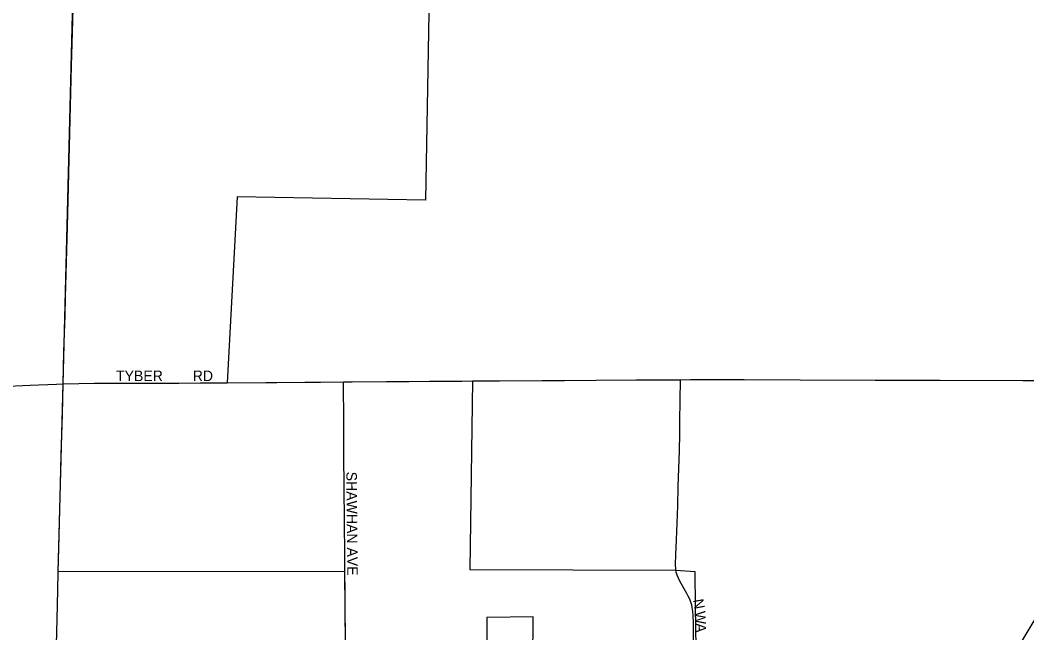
# Model space of a CAD drawing. Extents: x 1772825 to 1773716, y 1138558 to 1139032.
# Drawn here: x 1773338.15 to 1773356.3, y 1138902.61 to 1138913.65 of the extents above; entities that cross this region are included whole.
import ezdxf

# ---------------------------------------------------------------- set-up
doc = ezdxf.new("R2010")
doc.units = 0
for name, color, linetype in [('GM_X_City_Street', 7, 'Continuous'), ('GM_X_City_Street_Text', 7, 'Continuous'), ('GM_X_Corporation', 7, 'Continuous'), ('GM_X_County_Road', 7, 'Continuous'), ('GM_X_Township_Road', 7, 'Continuous')]:
    doc.layers.add(name, color=color, linetype=linetype)

msp = doc.modelspace()

# ---------------------------------------------------------------- linework, layer by layer
at = {"layer": 'GM_X_City_Street'}
for points in [[(1773338.923, 1138907.099), (1773339.493, 1138907.113), (1773340.34, 1138907.113), (1773341.011, 1138907.115), (1773341.396, 1138907.117), (1773341.884, 1138907.12)], [(1773344.007, 1138903.718), (1773344.003, 1138903.998), (1773343.998, 1138904.633), (1773343.987, 1138905.822), (1773343.984, 1138906.512), (1773343.979, 1138907.028), (1773343.978, 1138907.136)], [(1773344.019, 1138902.031), (1773344.018, 1138902.406), (1773344.016, 1138902.7), (1773344.013, 1138902.883), (1773344.01, 1138903.107), (1773344.009, 1138903.327), (1773344.007, 1138903.718)], [(1773350.292, 1138901.88), (1773350.293, 1138902.175), (1773350.293, 1138902.608), (1773350.289, 1138902.814), (1773350.286, 1138902.913), (1773350.285, 1138902.946), (1773350.282, 1138902.981), (1773350.28, 1138903.006), (1773350.275, 1138903.035), (1773350.269, 1138903.07), (1773350.259, 1138903.112), (1773350.238, 1138903.185), (1773350.224, 1138903.223), (1773350.198, 1138903.273), (1773350.17, 1138903.325), (1773350.047, 1138903.542), (1773349.996, 1138903.653), (1773349.984, 1138903.686), (1773349.979, 1138903.708), (1773349.975, 1138903.741)]]:
    msp.add_lwpolyline(points, dxfattribs=at)
at = {"layer": 'GM_X_Corporation'}
for points in [[(1773334.227, 1138900.103), (1773338.755, 1138900.152), (1773338.788, 1138900.602), (1773342.273, 1138900.611), (1773342.286, 1138900.627), (1773342.309, 1138900.637), (1773342.368, 1138900.64), (1773342.556, 1138900.646), (1773344.037, 1138900.647), (1773345.105, 1138900.66), (1773346.081, 1138900.659), (1773347.234, 1138900.674), (1773348.174, 1138900.678), (1773348.211, 1138901.289), (1773347.386, 1138901.3), (1773347.4, 1138902.902), (1773346.567, 1138902.891), (1773346.565, 1138902.359), (1773344.018, 1138902.392), (1773344.007, 1138903.718), (1773338.838, 1138903.71), (1773338.923, 1138907.099), (1773339.181, 1138917.089)], [(1773345.582, 1138917.161), (1773345.459, 1138910.409), (1773342.061, 1138910.472), (1773341.884, 1138907.12), (1773343.978, 1138907.136), (1773346.304, 1138907.152), (1773346.258, 1138903.753), (1773349.975, 1138903.741), (1773350.318, 1138903.719), (1773350.321, 1138903.081), (1773350.338, 1138901.979), (1773351.665, 1138901.948), (1773352.849, 1138901.918), (1773355.878, 1138901.897), (1773356.594, 1138903.099)]]:
    msp.add_lwpolyline(points, dxfattribs=at)
at = {"layer": 'GM_X_County_Road'}
for points in [[(1773338.923, 1138907.099), (1773338.938, 1138907.67), (1773338.954, 1138908.179), (1773338.959, 1138908.33), (1773338.968, 1138908.664), (1773339.001, 1138909.932), (1773339.078, 1138912.829), (1773339.096, 1138913.437), (1773339.112, 1138914.085), (1773339.146, 1138915.24), (1773339.164, 1138916.008), (1773339.184, 1138916.679), (1773339.19, 1138916.993), (1773339.228, 1138918.286)], [(1773328.765, 1138906.811), (1773328.999, 1138906.815), (1773329.371, 1138906.822), (1773329.659, 1138906.833), (1773330.03, 1138906.839), (1773330.366, 1138906.846), (1773330.855, 1138906.856), (1773332.442, 1138906.885), (1773333.1, 1138906.896), (1773333.612, 1138906.906), (1773333.759, 1138906.908), (1773333.867, 1138906.912), (1773334.33, 1138906.925), (1773335.61, 1138906.962), (1773337.399, 1138907.034), (1773337.797, 1138907.053), (1773338.331, 1138907.077), (1773338.803, 1138907.093), (1773338.923, 1138907.099)], [(1773338.838, 1138903.71), (1773338.848, 1138904.14), (1773338.876, 1138905.296), (1773338.891, 1138905.818), (1773338.911, 1138906.552), (1773338.923, 1138907.099)], [(1773338.769, 1138900.716), (1773338.788, 1138901.535), (1773338.8, 1138902.049), (1773338.806, 1138902.4), (1773338.816, 1138902.86), (1773338.83, 1138903.382), (1773338.838, 1138903.71)]]:
    msp.add_lwpolyline(points, dxfattribs=at)
at = {"layer": 'GM_X_Township_Road'}
for points in [[(1773341.884, 1138907.12), (1773342.78, 1138907.123), (1773343.563, 1138907.132), (1773343.978, 1138907.136)], [(1773343.978, 1138907.136), (1773344.135, 1138907.138), (1773345.167, 1138907.142), (1773346.112, 1138907.151), (1773346.304, 1138907.152)], [(1773346.304, 1138907.152), (1773346.795, 1138907.154), (1773347.565, 1138907.161), (1773347.963, 1138907.162), (1773348.535, 1138907.166), (1773349.256, 1138907.171), (1773350.057, 1138907.175)], [(1773349.975, 1138903.741), (1773349.974, 1138903.746), (1773349.972, 1138903.768), (1773349.97, 1138903.838), (1773349.973, 1138904.031), (1773349.979, 1138904.145), (1773349.995, 1138904.588), (1773350.008, 1138904.903), (1773350.018, 1138905.251), (1773350.038, 1138905.893), (1773350.048, 1138906.202), (1773350.047, 1138906.426), (1773350.057, 1138907.175)], [(1773350.057, 1138907.175), (1773350.238, 1138907.176), (1773351.207, 1138907.176), (1773352.214, 1138907.174), (1773353.569, 1138907.165), (1773354.737, 1138907.164), (1773356.229, 1138907.162), (1773357.783, 1138907.159), (1773358.553, 1138907.156), (1773359.473, 1138907.155), (1773359.834, 1138907.156), (1773360.033, 1138907.155), (1773360.34, 1138907.163)]]:
    msp.add_lwpolyline(points, dxfattribs=at)

# ---------------------------------------------------------------- texts
at = {"layer": 'GM_X_City_Street_Text'}
for s, height, rotation, p in [('TYBER', 0.1894, 0, (1773339.879, 1138907.15)), ('RD', 0.1894, 0, (1773341.262, 1138907.15)), ('SHAWHAN AVE', 0.18939, 270.5565, (1773344.031, 1138905.516)), ('N', 0.189, 280.4612, (1773350.281, 1138903.207)), ('W', 0.189, 273.9371, (1773350.315, 1138902.999)), ('A', 0.189, 270.4372, (1773350.33, 1138902.786))]:
    msp.add_text(s, height=height, rotation=rotation, dxfattribs=at).set_placement(p)

doc.saveas('drawing.dxf')
